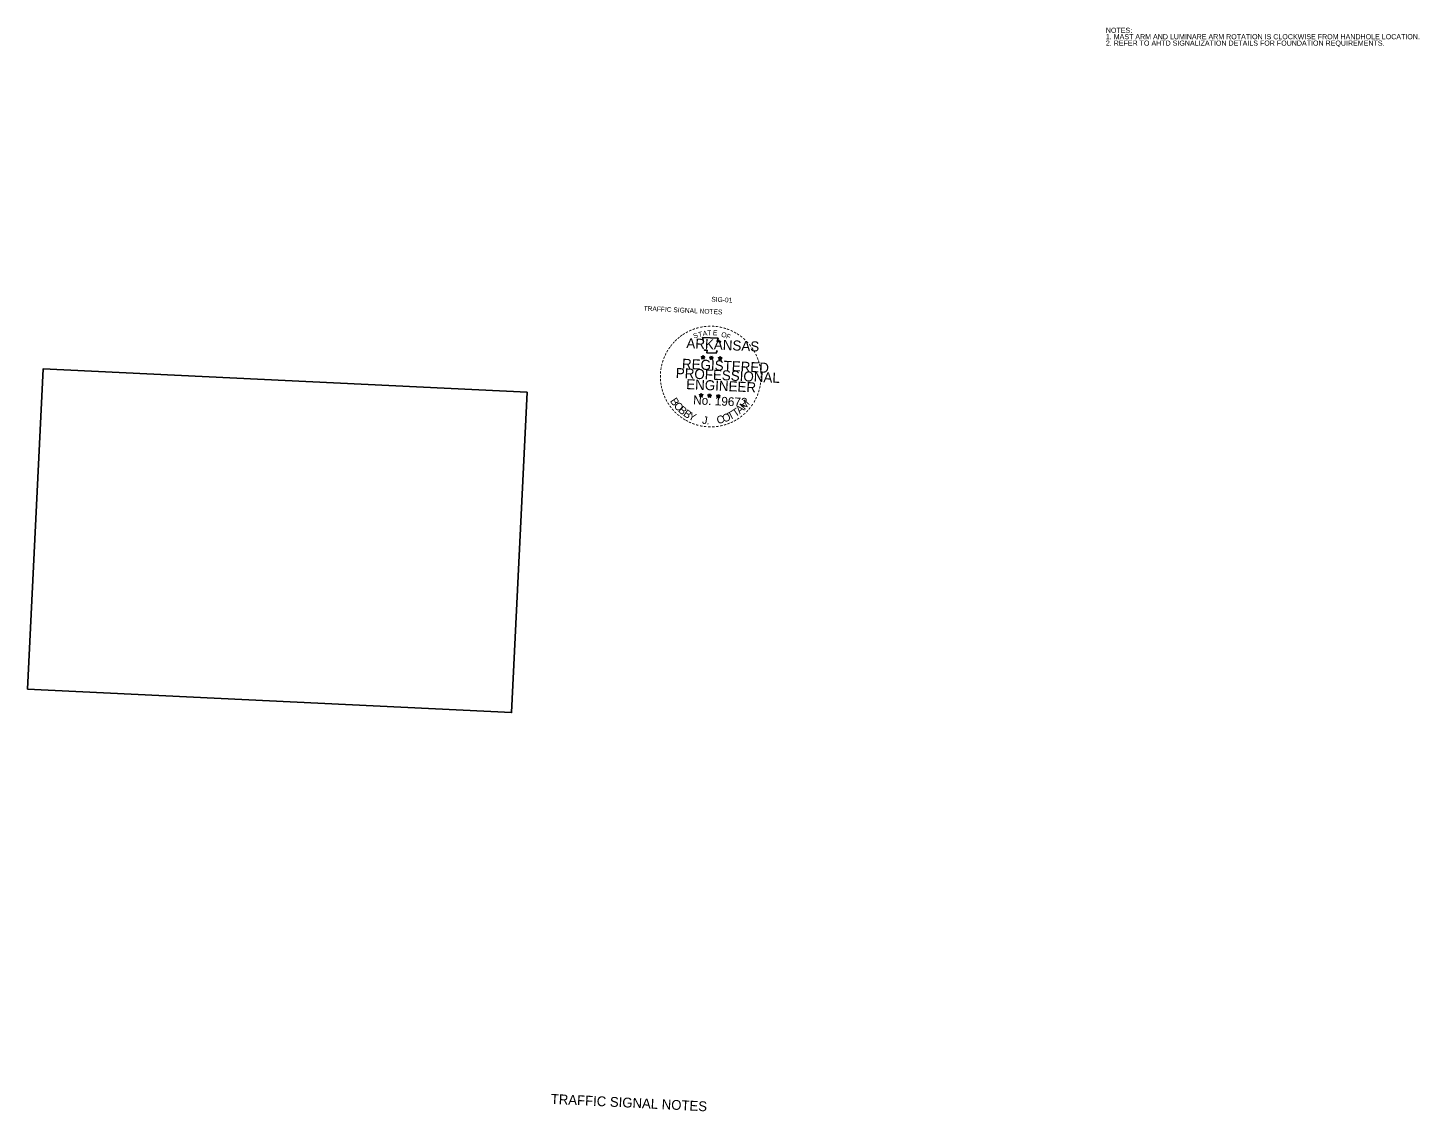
# Model space of a CAD drawing. Extents: x 660985 to 662601, y 642519 to 643065.
# Drawn here: x 661927 to 662601, y 642536 to 643065 of the extents above; entities that cross this region are included whole.
import ezdxf

# ---------------------------------------------------------------- set-up
doc = ezdxf.new("R2010")
doc.units = 0
for name, color, linetype in [('R_Border', 7, 'Continuous'), ('R_Horz Alg Annot', 7, 'Continuous'), ('T_Detection Zones', 7, 'Continuous'), ('TEXT', 7, 'Continuous')]:
    doc.layers.add(name, color=color, linetype=linetype)

msp = doc.modelspace()

# ---------------------------------------------------------------- linework, layer by layer
at = {"layer": 'R_Border'}
for p, q in [((662255.39, 642904.23), (662256.23, 642903.92)), ((662255.39, 642904.23), (662256, 642904.09)), ((662255.39, 642904.23), (662255.96, 642903.9)), ((662256.27, 642904.81), (662256.14, 642904.2)), ((662256.23, 642903.92), (662256.27, 642904.81)), ((662257.09, 642904.15), (662256.23, 642903.92)), ((662256.27, 642904.81), (662256.36, 642904.19)), ((662257.09, 642904.15), (662256.39, 642904.06)), ((662257.09, 642904.15), (662256.58, 642903.92)), ((662260.35, 642904.61), (662260.22, 642904)), ((662260.3, 642903.72), (662260.35, 642904.61)), ((662260.35, 642904.61), (662260.44, 642903.99)), ((662264.65, 642904.37), (662264.52, 642903.76)), ((662264.6, 642903.48), (662264.65, 642904.37)), ((662264.65, 642904.37), (662264.74, 642903.76)), ((662255.67, 642903.22), (662256.23, 642903.92)), ((662255.67, 642903.22), (662256.01, 642903.8)), ((662255.67, 642903.22), (662256.22, 642903.72)), ((662256.72, 642903.17), (662256.22, 642903.72)), ((662256.72, 642903.17), (662256.23, 642903.92)), ((662256.72, 642903.17), (662256.42, 642903.89)), ((662259.47, 642904.03), (662260.3, 642903.72)), ((662259.47, 642904.03), (662260.08, 642903.89)), ((662259.47, 642904.03), (662260.03, 642903.71)), ((662259.74, 642903.02), (662260.3, 642903.72)), ((662259.74, 642903.02), (662260.08, 642903.6)), ((662259.74, 642903.02), (662260.29, 642903.53)), ((662260.79, 642902.97), (662260.29, 642903.52)), ((662261.16, 642903.95), (662260.3, 642903.72)), ((662260.79, 642902.97), (662260.3, 642903.72)), ((662261.16, 642903.95), (662260.46, 642903.86)), ((662260.79, 642902.97), (662260.49, 642903.7)), ((662261.16, 642903.95), (662260.65, 642903.72)), ((662263.77, 642903.79), (662264.6, 642903.48)), ((662263.77, 642903.79), (662264.38, 642903.65)), ((662263.77, 642903.79), (662264.33, 642903.47)), ((662264.04, 642902.78), (662264.6, 642903.48)), ((662264.04, 642902.78), (662264.38, 642903.36)), ((662264.04, 642902.78), (662264.59, 642903.29)), ((662265.09, 642902.73), (662264.59, 642903.28)), ((662265.46, 642903.71), (662264.6, 642903.48)), ((662265.09, 642902.73), (662264.6, 642903.48)), ((662265.46, 642903.71), (662264.76, 642903.63)), ((662265.09, 642902.73), (662264.79, 642903.46)), ((662265.46, 642903.71), (662264.95, 642903.49)), ((662254.49, 642885.76), (662255.32, 642885.45)), ((662254.49, 642885.76), (662255.1, 642885.62)), ((662254.49, 642885.76), (662255.05, 642885.44)), ((662254.76, 642884.75), (662255.32, 642885.45)), ((662254.76, 642884.75), (662255.1, 642885.33)), ((662254.76, 642884.75), (662255.31, 642885.25)), ((662255.37, 642886.34), (662255.24, 642885.73)), ((662255.81, 642884.7), (662255.31, 642885.25)), ((662255.32, 642885.45), (662255.37, 642886.34)), ((662256.18, 642885.68), (662255.32, 642885.45)), ((662255.81, 642884.7), (662255.32, 642885.45)), ((662255.37, 642886.34), (662255.46, 642885.72)), ((662256.18, 642885.68), (662255.48, 642885.59)), ((662255.81, 642884.7), (662255.51, 642885.43)), ((662256.18, 642885.68), (662255.67, 642885.45)), ((662258.56, 642885.56), (662259.39, 642885.25)), ((662258.56, 642885.56), (662259.17, 642885.42)), ((662258.56, 642885.56), (662259.12, 642885.24)), ((662258.83, 642884.55), (662259.39, 642885.25)), ((662258.83, 642884.55), (662259.17, 642885.13)), ((662258.83, 642884.55), (662259.38, 642885.06)), ((662259.44, 642886.14), (662259.31, 642885.53)), ((662259.88, 642884.5), (662259.38, 642885.05)), ((662259.39, 642885.25), (662259.44, 642886.14)), ((662260.25, 642885.48), (662259.39, 642885.25)), ((662259.88, 642884.5), (662259.39, 642885.25)), ((662259.44, 642886.14), (662259.53, 642885.53)), ((662260.25, 642885.48), (662259.55, 642885.4)), ((662259.88, 642884.5), (662259.58, 642885.23)), ((662260.25, 642885.48), (662259.74, 642885.26)), ((662262.86, 642885.33), (662263.7, 642885.02)), ((662262.86, 642885.33), (662263.48, 642885.19)), ((662262.86, 642885.33), (662263.43, 642885)), ((662263.14, 642884.32), (662263.7, 642885.02)), ((662263.14, 642884.32), (662263.48, 642884.9)), ((662263.14, 642884.32), (662263.69, 642884.82)), ((662263.75, 642885.91), (662263.62, 642885.3)), ((662264.19, 642884.27), (662263.69, 642884.82)), ((662263.7, 642885.02), (662263.75, 642885.91)), ((662264.56, 642885.25), (662263.7, 642885.02)), ((662264.19, 642884.27), (662263.7, 642885.02)), ((662263.75, 642885.91), (662263.84, 642885.29)), ((662264.56, 642885.25), (662263.86, 642885.16)), ((662264.19, 642884.27), (662263.89, 642884.99)), ((662264.56, 642885.25), (662264.05, 642885.02))]:
    msp.add_line(p, q, dxfattribs=at)
for points in [[(662255.95, 642913.68), (662256.51, 642911.63)], [(662264.41, 642911.02), (662264.79, 642911.69), (662263.11, 642911.72), (662263.55, 642913.31), (662255.95, 642913.68)], [(662256.27, 642904.81), (662256.72, 642903.17), (662255.39, 642904.23), (662257.09, 642904.15), (662255.67, 642903.22), (662256.27, 642904.81)], [(662256.87, 642907.72), (662256.86, 642907.5), (662258.23, 642907.39), (662258.04, 642906.24), (662262.6, 642906.02), (662263.15, 642907.3)], [(662260.35, 642904.61), (662260.79, 642902.97), (662259.47, 642904.03), (662261.16, 642903.95), (662259.74, 642903.02), (662260.35, 642904.61)], [(662264.65, 642904.37), (662265.09, 642902.73), (662263.77, 642903.79), (662265.46, 642903.71), (662264.04, 642902.78), (662264.65, 642904.37)], [(662255.37, 642886.34), (662255.81, 642884.7), (662254.49, 642885.76), (662256.18, 642885.68), (662254.76, 642884.75), (662255.37, 642886.34)], [(662259.44, 642886.14), (662259.88, 642884.5), (662258.56, 642885.56), (662260.25, 642885.48), (662258.83, 642884.55), (662259.44, 642886.14)], [(662263.75, 642885.91), (662264.19, 642884.27), (662262.86, 642885.33), (662264.56, 642885.25), (662263.14, 642884.32), (662263.75, 642885.91)]]:
    msp.add_lwpolyline(points, dxfattribs=at)
for centre, radius in [((662256.23, 642903.92), 0.421), ((662256.23, 642903.92), 0.353), ((662256.23, 642903.92), 0.283), ((662256.23, 642903.92), 0.242), ((662260.3, 642903.72), 0.421), ((662256.23, 642903.92), 0.182), ((662256.23, 642903.92), 0.121), ((662256.23, 642903.92), 0.0724), ((662260.3, 642903.72), 0.353), ((662260.3, 642903.72), 0.283), ((662260.3, 642903.72), 0.242), ((662260.3, 642903.72), 0.182), ((662260.3, 642903.72), 0.121), ((662260.3, 642903.72), 0.0724), ((662264.6, 642903.48), 0.421), ((662264.6, 642903.48), 0.353), ((662264.6, 642903.48), 0.283), ((662264.6, 642903.48), 0.242), ((662264.6, 642903.48), 0.182), ((662264.6, 642903.48), 0.121), ((662264.6, 642903.48), 0.0724), ((662255.32, 642885.45), 0.421), ((662255.32, 642885.45), 0.353), ((662255.32, 642885.45), 0.283), ((662255.32, 642885.45), 0.242), ((662255.32, 642885.45), 0.182), ((662255.32, 642885.45), 0.121), ((662255.32, 642885.45), 0.0724), ((662259.39, 642885.25), 0.421), ((662259.39, 642885.25), 0.353), ((662259.39, 642885.25), 0.283), ((662259.39, 642885.25), 0.242), ((662259.39, 642885.25), 0.182), ((662259.39, 642885.25), 0.121), ((662259.39, 642885.25), 0.0724), ((662263.7, 642885.02), 0.421), ((662263.7, 642885.02), 0.353), ((662263.7, 642885.02), 0.283), ((662263.7, 642885.02), 0.242), ((662263.7, 642885.02), 0.182), ((662263.7, 642885.02), 0.121), ((662263.7, 642885.02), 0.0724)]:
    msp.add_circle(centre, radius, dxfattribs=at)
at = {"layer": 'T_Detection Zones'}
msp.add_lwpolyline([(661926.64, 642742.2), (662162.82, 642730.73), (662170.4, 642886.96), (661934.22, 642898.43)], close=True, dxfattribs=at)

# ---------------------------------------------------------------- texts
at = {"layer": 'R_Border'}
for s, height, rotation, p in [('SIG-01', 2.345, 357.21992, (662260.21, 642931.17)), ('TRAFFIC SIGNAL NOTES', 2.3448, 357.21992, (662227.17, 642926.73)), ('-', 3.91, 21.52555, (662251.45, 642916)), ('-', 3.91, 16.39442, (662253.03, 642916.58)), ('-', 3.91, 10.84848, (662254.89, 642917.08)), ('-', 3.91, 7.43768, (662256.56, 642917.39)), ('-', 3.91, 3.11516, (662258.35, 642917.57)), ('-', 3.91, 357.40456, (662260.25, 642917.66)), ('-', 3.91, 354.96138, (662262.01, 642917.54)), ('-', 3.91, 349.38006, (662263.81, 642917.32)), ('-', 3.91, 344.42323, (662265.55, 642916.95)), ('-', 3.91, 339.55453, (662267.08, 642916.5)), ('-', 3.91, 47.83251, (662242.42, 642909.49)), ('-', 3.91, 45.64138, (662243.46, 642910.63)), ('-', 3.91, 40.18058, (662244.61, 642911.74)), ('-', 3.91, 36.16899, (662245.71, 642912.71)), ('-', 3.91, 33.45007, (662246.92, 642913.57)), ('-', 3.91, 31.2819, (662248.37, 642914.47)), ('ARKANSAS', 4.883, 357.21833, (662248.01, 642908.48)), ('-', 3.91, 26.01015, (662249.87, 642915.3)), ('S', 2.44, 18.81235, (662251.9, 642913.09)), ('T', 2.44, 13.62193, (662254.17, 642913.79)), ('A', 2.44, 8.43151, (662256.22, 642914.31)), ('T', 2.44, 3.24109, (662258.31, 642914.61)), ('E', 2.44, 358.05067, (662261.01, 642914.75)), ('O', 2.44, 347.66983, (662264.9, 642914.04)), ('F', 2.44, 337.289, (662267.2, 642913.38)), ('-', 3.91, 335.07343, (662268.85, 642915.87)), ('-', 3.91, 331.33943, (662270.36, 642915.13)), ('-', 3.91, 326.85923, (662271.74, 642914.38)), ('-', 3.91, 323.08099, (662273.26, 642913.42)), ('-', 3.91, 317.74804, (662274.7, 642912.31)), ('-', 3.91, 312.79692, (662276.1, 642911.05)), ('-', 3.91, 69.61281, (662238.34, 642902.48)), ('-', 3.91, 64.9926, (662238.95, 642903.99)), ('-', 3.91, 60.08968, (662239.65, 642905.45)), ('-', 3.91, 55.28896, (662240.49, 642906.91)), ('-', 3.91, 51.45081, (662241.34, 642908.16)), ('-', 3.91, 307.09806, (662277.42, 642909.64)), ('-', 3.91, 303.87051, (662278.63, 642908.11)), ('-', 3.42, 300.89363, (662279.75, 642906.66)), ('-', 3.91, 296.88669, (662280.46, 642905.15)), ('-', 3.91, 82.40467, (662237.1, 642897.36)), ('-', 3.91, 78.4196, (662237.37, 642899.04)), ('-', 3.91, 72.67929, (662237.77, 642900.76)), ('PROFESSIONAL', 4.8833, 357.21833, (662242.84, 642893.93)), ('REGISTERED', 4.883, 357.21833, (662245.86, 642898.44)), ('-', 3.91, 291.88113, (662281.17, 642903.62)), ('-', 3.91, 287.79116, (662281.73, 642902.18)), ('-', 3.91, 282.3416, (662282.24, 642900.74)), ('-', 3.91, 277.76767, (662282.64, 642898.9)), ('-', 3.91, 96.16626, (662237.05, 642892.25)), ('-', 3.91, 91.41422, (662236.96, 642893.89)), ('-', 3.91, 86.28057, (662236.96, 642895.66)), ('-', 3.91, 98.93328, (662237.29, 642890.45)), ('ENGINEER', 4.883, 357.21833, (662247.92, 642888.49)), ('-', 3.91, 260.73553, (662282.88, 642892.07)), ('-', 3.91, 267.159, (662283.01, 642893.7)), ('-', 3.91, 273.81449, (662282.94, 642897.01)), ('-', 3.91, 271.54844, (662283, 642895.24)), ('-', 3.91, 102.67618, (662237.62, 642888.98)), ('-', 3.91, 106.30575, (662238.07, 642887.41)), ('-', 3.91, 111.28265, (662238.62, 642885.93)), ('-', 3.91, 112.94718, (662239.29, 642884.39)), ('B', 3.76, 304.07319, (662239.95, 642882.68)), ('No. 19672', 4.29, 357.21833, (662251.35, 642881.11)), ('-', 3.91, 245.107, (662281.13, 642885.5)), ('-', 3.91, 250.08642, (662281.76, 642887.11)), ('-', 3.91, 252.98094, (662282.28, 642888.85)), ('-', 3.91, 258.21362, (662282.63, 642890.49)), ('-', 3.91, 117.66545, (662240.09, 642882.91)), ('-', 3.91, 123.11178, (662241.01, 642881.5)), ('-', 3.91, 127.93645, (662242.07, 642880.1)), ('-', 3.91, 131.44215, (662243.26, 642878.71)), ('-', 3.91, 136.15216, (662244.49, 642877.51)), ('O', 3.76, 312.18337, (662241.68, 642880.12)), ('B', 3.76, 317.96399, (662243.8, 642877.79)), ('B', 3.76, 326.07417, (662246.23, 642875.71)), ('Y', 3.76, 334.18435, (662248.71, 642874.11)), ('T', 3.76, 27.35609, (662269.32, 642873.24)), ('T', 3.76, 34.23693, (662272.02, 642874.7)), ('A', 3.76, 40.13725, (662274.17, 642876.16)), ('M', 3.76, 48.24743, (662276.53, 642878.17)), ('-', 3.91, 228.47211, (662277.2, 642879.33)), ('-', 3.91, 231.06358, (662278.31, 642880.66)), ('-', 3.91, 236.28958, (662279.37, 642882.21)), ('-', 3.91, 241.83805, (662280.42, 642884)), ('-', 3.91, 141.86467, (662245.8, 642876.46)), ('-', 3.91, 145.30812, (662247.12, 642875.49)), ('-', 3.91, 148.78873, (662248.49, 642874.62)), ('-', 3.91, 151.81853, (662249.74, 642873.96)), ('-', 3.91, 155.77955, (662251.23, 642873.27)), ('-', 3.91, 160.0166, (662252.88, 642872.67)), ('-', 3.91, 164.77385, (662254.6, 642872.18)), ('-', 3.91, 170.3338, (662256.47, 642871.82)), ('J', 3.76, 350.5606, (662255.61, 642871.66)), ('-', 3.91, 173.7366, (662258.29, 642871.6)), ('.', 3.76, 350.5606, (662257.9, 642871.36)), ('-', 3.91, 188.50409, (662263.9, 642871.89)), ('C', 3.76, 11.13573, (662263.27, 642871.47)), ('-', 3.91, 192.69263, (662265.7, 642872.29)), ('O', 3.76, 19.24591, (662266.38, 642872.16)), ('-', 3.91, 197.93676, (662267.38, 642872.8)), ('-', 3.91, 201.46995, (662268.92, 642873.39)), ('-', 3.91, 204.57517, (662270.48, 642874.09)), ('-', 3.91, 209.46742, (662271.88, 642874.87)), ('-', 3.91, 212.95467, (662273.23, 642875.75)), ('-', 3.91, 218.30342, (662274.63, 642876.84)), ('-', 3.91, 222.98367, (662275.96, 642878.02)), ('-', 3.91, 178.62152, (662260.24, 642871.55)), ('-', 3.91, 183.035, (662262.09, 642871.65))]:
    msp.add_text(s, height=height, rotation=rotation, dxfattribs=at).set_placement(p)
at = {"layer": 'R_Horz Alg Annot'}
msp.add_text('TRAFFIC SIGNAL NOTES', height=4.8, rotation=357.21992, dxfattribs=at).set_placement((662181.83, 642539.92))
at = {"layer": 'TEXT'}
for s, p in [('1. MAST ARM AND LUMINARE ARM ROTATION IS CLOCKWISE FROM HANDHOLE LOCATION.', (662452.8, 643059.1)), ('NOTES:', (662452.8, 643062.23)), ('2. REFER TO AHTD SIGNALIZATION DETAILS FOR FOUNDATION REQUIREMENTS.', (662452.8, 643055.97))]:
    msp.add_text(s, height=2.5, rotation=360, dxfattribs=at).set_placement(p)

doc.saveas('drawing.dxf')
